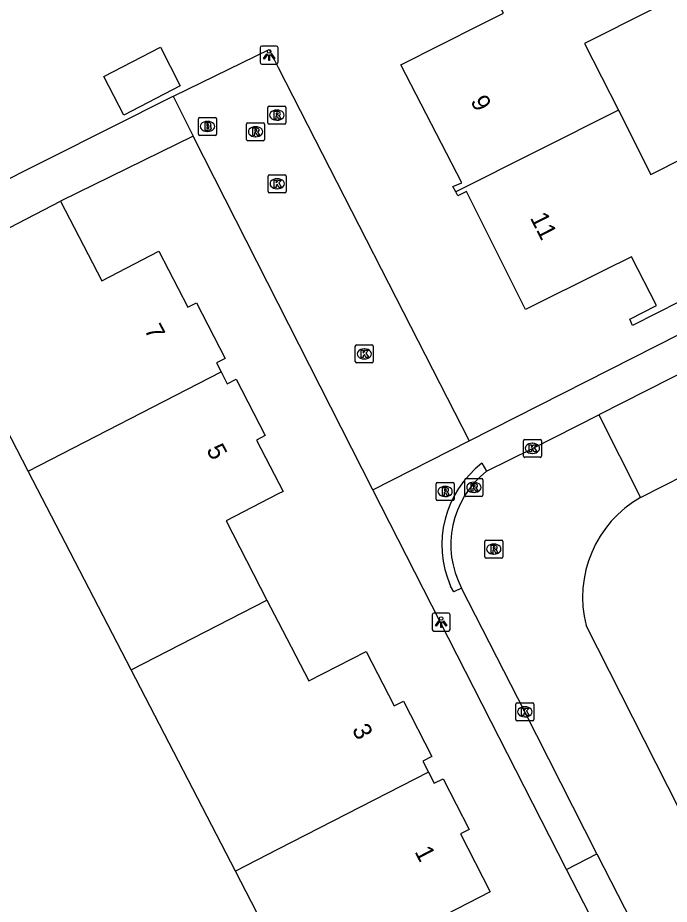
# Model space of a CAD drawing. Extents: x 162722 to 165099, y 384721 to 386283.
# Drawn here: x 163985.51 to 164021.74, y 385039.4 to 385088.69 of the extents above; entities that cross this region are included whole.
import ezdxf

# ---------------------------------------------------------------- set-up
doc = ezdxf.new("R2010")
doc.units = 0
for name, color, linetype in [('IMGEO_Brandkraan', 7, 'Continuous'), ('IMGEO_Kolk', 7, 'Continuous'), ('IMGEO_Lichtpunt', 7, 'Continuous'), ('IMGEO_Pand', 7, 'Continuous'), ('IMGEO_Pand_nummerreeks', 7, 'Continuous'), ('IMGEO_Rijbaan_lokaal_open', 7, 'Continuous'), ('IMGEO_Rioolput', 7, 'Continuous'), ('IMGEO_Voetpad_open', 7, 'Continuous')]:
    doc.layers.add(name, color=color, linetype=linetype)

msp = doc.modelspace()

# ---------------------------------------------------------------- linework, layer by layer
at = {"layer": 'IMGEO_Brandkraan'}
for p, q in [((163995.563, 385082.219), (163995.563, 385083.071)), ((163995.638, 385083.145), (163996.49, 385083.145)), ((163996.051, 385082.925), (163996.076, 385082.925)), ((163996.564, 385083.071), (163996.564, 385082.219)), ((163996.074, 385082.365), (163996.049, 385082.365)), ((163996.49, 385082.145), (163995.638, 385082.145))]:
    msp.add_line(p, q, dxfattribs=at)
for points in [[(163995.563, 385082.219), (163995.563, 385083.071)], [(163995.638, 385083.145), (163996.49, 385083.145)], [(163995.911, 385082.845), (163995.911, 385082.445), (163996.124, 385082.445)], [(163996.142, 385082.845), (163995.911, 385082.845)], [(163996.564, 385083.071), (163996.564, 385082.219)], [(163996.09, 385082.764), (163996.036, 385082.764), (163996.036, 385082.688)], [(163996.036, 385082.688), (163996.089, 385082.688)], [(163996.098, 385082.612), (163996.036, 385082.612), (163996.036, 385082.531)], [(163996.036, 385082.531), (163996.098, 385082.531)], [(163996.49, 385082.145), (163995.638, 385082.145)]]:
    msp.add_lwpolyline(points, dxfattribs=at)
for centre, radius, start, end in [((163995.64, 385083.069), 0.0765, 91.552, 178.448), ((163995.64, 385083.069), 0.0765, 91.552, 178.448), ((163996.146, 385082.7), 0.145, 59.4692, 91.5367), ((163996.171, 385082.747), 0.0922, 285.5137, 58.1501), ((163996.488, 385083.069), 0.0765, 1.552, 88.448), ((163996.488, 385083.069), 0.0765, 1.552, 88.448), ((163996.091, 385082.726), 0.0379, 267.8285, 90.9355), ((163996.099, 385082.571), 0.0404, 269.8759, 90.5077), ((163996.13, 385082.696), 0.251, 268.6676, 293.5347), ((163996.176, 385082.555), 0.105, 301.3115, 78.989), ((163995.64, 385082.221), 0.0765, 181.552, 268.448), ((163995.64, 385082.221), 0.0765, 181.552, 268.448), ((163996.488, 385082.221), 0.0765, 271.552, 358.448), ((163996.488, 385082.221), 0.0765, 271.552, 358.448)]:
    msp.add_arc(centre, radius, start, end, dxfattribs=at)
for centre, major_axis, ratio, start_param, end_param in [((163996.05, 385082.645), (-0.387, 0.002), 0.722429, 4.712389, 7.853982), ((163996.075, 385082.645), (-0.39, 0.002), 0.717154, 1.570796, 4.712389)]:
    msp.add_ellipse(centre, major_axis=major_axis, ratio=ratio, start_param=start_param, end_param=end_param, dxfattribs=at)
at = {"layer": 'IMGEO_Kolk'}
for p, q in [((163999.444, 385079.032), (163999.444, 385079.884)), ((163999.519, 385079.958), (164000.371, 385079.958)), ((164000.445, 385079.884), (164000.445, 385079.032)), ((163999.932, 385079.738), (163999.957, 385079.738)), ((164000.371, 385078.958), (163999.519, 385078.958)), ((163999.955, 385079.178), (163999.93, 385079.178)), ((164004.36, 385070.498), (164005.212, 385070.498)), ((164004.285, 385069.572), (164004.285, 385070.424)), ((164004.773, 385070.278), (164004.798, 385070.278)), ((164005.286, 385070.424), (164005.286, 385069.572)), ((164004.796, 385069.718), (164004.771, 385069.718)), ((164005.212, 385069.498), (164004.36, 385069.498)), ((164013.631, 385064.321), (164013.631, 385065.173)), ((164013.706, 385065.247), (164014.558, 385065.247)), ((164014.632, 385065.173), (164014.632, 385064.321)), ((164014.119, 385065.027), (164014.144, 385065.027)), ((164014.558, 385064.247), (164013.706, 385064.247)), ((164014.142, 385064.467), (164014.117, 385064.467)), ((164013.21, 385049.672), (164013.21, 385050.524)), ((164013.285, 385050.598), (164014.137, 385050.598)), ((164013.698, 385050.378), (164013.723, 385050.378)), ((164014.211, 385050.524), (164014.211, 385049.672)), ((164013.721, 385049.818), (164013.696, 385049.818)), ((164014.137, 385049.598), (164013.285, 385049.598))]:
    msp.add_line(p, q, dxfattribs=at)
for points in [[(163999.444, 385079.032), (163999.444, 385079.884)], [(163999.519, 385079.958), (164000.371, 385079.958)], [(164000.445, 385079.884), (164000.445, 385079.032)], [(163999.765, 385079.658), (163999.888, 385079.658), (163999.888, 385079.507), (164000.018, 385079.658), (164000.182, 385079.658), (164000.036, 385079.507), (164000.189, 385079.258), (164000.037, 385079.258), (163999.952, 385079.422), (163999.888, 385079.355), (163999.888, 385079.258), (163999.765, 385079.258), (163999.765, 385079.658)], [(164000.371, 385078.958), (163999.519, 385078.958)], [(164004.36, 385070.498), (164005.212, 385070.498)], [(164004.285, 385069.572), (164004.285, 385070.424)], [(164004.606, 385070.198), (164004.729, 385070.198), (164004.729, 385070.047), (164004.859, 385070.198), (164005.023, 385070.198), (164004.877, 385070.047), (164005.03, 385069.798), (164004.878, 385069.798), (164004.793, 385069.962), (164004.729, 385069.895), (164004.729, 385069.798), (164004.606, 385069.798), (164004.606, 385070.198)], [(164005.286, 385070.424), (164005.286, 385069.572)], [(164005.212, 385069.498), (164004.36, 385069.498)], [(164013.631, 385064.321), (164013.631, 385065.173)], [(164013.706, 385065.247), (164014.558, 385065.247)], [(164014.632, 385065.173), (164014.632, 385064.321)], [(164013.952, 385064.947), (164014.075, 385064.947), (164014.075, 385064.796), (164014.205, 385064.947), (164014.369, 385064.947), (164014.223, 385064.796), (164014.376, 385064.547), (164014.224, 385064.547), (164014.139, 385064.711), (164014.075, 385064.644), (164014.075, 385064.547), (164013.952, 385064.547), (164013.952, 385064.947)], [(164014.558, 385064.247), (164013.706, 385064.247)], [(164013.21, 385049.672), (164013.21, 385050.524)], [(164013.285, 385050.598), (164014.137, 385050.598)], [(164013.531, 385050.298), (164013.654, 385050.298), (164013.654, 385050.147), (164013.784, 385050.298), (164013.948, 385050.298), (164013.802, 385050.147), (164013.955, 385049.898), (164013.803, 385049.898), (164013.718, 385050.062), (164013.654, 385049.995), (164013.654, 385049.898), (164013.531, 385049.898), (164013.531, 385050.298)], [(164014.211, 385050.524), (164014.211, 385049.672)], [(164014.137, 385049.598), (164013.285, 385049.598)]]:
    msp.add_lwpolyline(points, dxfattribs=at)
for centre, start, end in [((163999.521, 385079.882), 91.552, 178.448), ((163999.521, 385079.882), 91.552, 178.448), ((164000.369, 385079.882), 1.552, 88.448), ((164000.369, 385079.882), 1.552, 88.448), ((163999.521, 385079.034), 181.552, 268.448), ((163999.521, 385079.034), 181.552, 268.448), ((164000.369, 385079.034), 271.552, 358.448), ((164000.369, 385079.034), 271.552, 358.448), ((164004.362, 385070.422), 91.552, 178.448), ((164004.362, 385070.422), 91.552, 178.448), ((164005.21, 385070.422), 1.552, 88.448), ((164005.21, 385070.422), 1.552, 88.448), ((164004.362, 385069.574), 181.552, 268.448), ((164004.362, 385069.574), 181.552, 268.448), ((164005.21, 385069.574), 271.552, 358.448), ((164005.21, 385069.574), 271.552, 358.448), ((164013.708, 385065.171), 91.552, 178.448), ((164013.708, 385065.171), 91.552, 178.448), ((164014.556, 385065.171), 1.552, 88.448), ((164014.556, 385065.171), 1.552, 88.448), ((164013.708, 385064.323), 181.552, 268.448), ((164013.708, 385064.323), 181.552, 268.448), ((164014.556, 385064.323), 271.552, 358.448), ((164014.556, 385064.323), 271.552, 358.448), ((164013.287, 385050.522), 91.552, 178.448), ((164013.287, 385050.522), 91.552, 178.448), ((164014.135, 385050.522), 1.552, 88.448), ((164014.135, 385050.522), 1.552, 88.448), ((164013.287, 385049.674), 181.552, 268.448), ((164013.287, 385049.674), 181.552, 268.448), ((164014.135, 385049.674), 271.552, 358.448), ((164014.135, 385049.674), 271.552, 358.448)]:
    msp.add_arc(centre, 0.0765, start, end, dxfattribs=at)
for centre, major_axis, ratio, start_param, end_param in [((163999.931, 385079.458), (-0.387, 0.002), 0.722429, 4.712389, 7.853982), ((163999.956, 385079.458), (-0.39, 0.002), 0.717154, 1.570796, 4.712389), ((164004.772, 385069.998), (-0.387, 0.002), 0.722429, 4.712389, 7.853982), ((164004.797, 385069.998), (-0.39, 0.002), 0.717154, 1.570796, 4.712389), ((164014.118, 385064.747), (-0.387, 0.002), 0.722429, 4.712389, 7.853982), ((164014.143, 385064.747), (-0.39, 0.002), 0.717154, 1.570796, 4.712389), ((164013.697, 385050.098), (-0.387, 0.002), 0.722429, 4.712389, 7.853982), ((164013.722, 385050.098), (-0.39, 0.002), 0.717154, 1.570796, 4.712389)]:
    msp.add_ellipse(centre, major_axis=major_axis, ratio=ratio, start_param=start_param, end_param=end_param, dxfattribs=at)
at = {"layer": 'IMGEO_Lichtpunt'}
for p, q in [((163998.994, 385087.017), (163998.994, 385086.21)), ((163998.994, 385087.017), (163998.994, 385086.21)), ((163999.896, 385087.112), (163999.088, 385087.112)), ((163999.896, 385087.112), (163999.088, 385087.112)), ((163999.99, 385086.21), (163999.99, 385087.017)), ((163999.99, 385086.21), (163999.99, 385087.017)), ((163999.088, 385086.116), (163999.896, 385086.116)), ((163999.088, 385086.116), (163999.896, 385086.116)), ((164008.561, 385055.488), (164008.561, 385054.681)), ((164008.561, 385055.488), (164008.561, 385054.681)), ((164009.463, 385055.583), (164008.655, 385055.583)), ((164009.463, 385055.583), (164008.655, 385055.583)), ((164009.557, 385054.681), (164009.557, 385055.488)), ((164009.557, 385054.681), (164009.557, 385055.488)), ((164008.655, 385054.587), (164009.463, 385054.587)), ((164008.655, 385054.587), (164009.463, 385054.587))]:
    msp.add_line(p, q, dxfattribs=at)
for points in [[(163999.368, 385086.681), (163999.407, 385086.653), (163999.219, 385086.391), (163999.181, 385086.418), (163999.368, 385086.681)], [(163999.47, 385086.633), (163999.517, 385086.633), (163999.517, 385086.311), (163999.47, 385086.311), (163999.47, 385086.633)], [(163999.58, 385086.653), (163999.618, 385086.68), (163999.805, 385086.418), (163999.766, 385086.39), (163999.58, 385086.653)], [(164008.935, 385055.152), (164008.974, 385055.124), (164008.786, 385054.862), (164008.748, 385054.889), (164008.935, 385055.152)], [(164009.037, 385055.104), (164009.084, 385055.104), (164009.084, 385054.782), (164009.037, 385054.782), (164009.037, 385055.104)], [(164009.147, 385055.124), (164009.185, 385055.151), (164009.372, 385054.889), (164009.333, 385054.861), (164009.147, 385055.124)]]:
    msp.add_lwpolyline(points, dxfattribs=at)
for centre in [(163999.493, 385086.815), (164009.06, 385055.286)]:
    msp.add_circle(centre, 0.0994, dxfattribs=at)
for centre, start, end in [((163999.088, 385087.017), 90, 180), ((163999.088, 385087.017), 90, 180), ((163999.896, 385087.017), 0, 90), ((163999.896, 385087.017), 0, 90), ((163999.088, 385086.21), 180, 270), ((163999.088, 385086.21), 180, 270), ((163999.896, 385086.21), 270, 0), ((163999.896, 385086.21), 270, 360), ((164008.655, 385055.488), 90, 180), ((164008.655, 385055.488), 90, 180), ((164009.463, 385055.488), 0, 90), ((164009.463, 385055.488), 0, 90), ((164008.655, 385054.681), 180, 270), ((164008.655, 385054.681), 180, 270), ((164009.463, 385054.681), 270, 0), ((164009.463, 385054.681), 270, 360)]:
    msp.add_arc(centre, 0.0946, start, end, dxfattribs=at)
at = {"layer": 'IMGEO_Pand'}
for points in [[(164009.873, 385079.005), (164009.715, 385079.311), (164010.213, 385079.511), (164006.813, 385086.073), (164011.225, 385088.298), (164012.52, 385088.951), (164011.134, 385091.702), (164009.785, 385091.022), (164009.615, 385091.362), (164014.08, 385093.614), (164017.599, 385095.388), (164020.752, 385089.137), (164017.038, 385087.265), (164018.915, 385083.544)], [(163994.552, 385084.909), (163991.41, 385083.281), (163990.302, 385085.419), (163993.444, 385087.047), (163994.552, 385084.909)], [(164018.915, 385083.544), (164020.718, 385079.969), (164024.433, 385081.843), (164025.345, 385080.037), (164025.622, 385079.488), (164027.599, 385075.574), (164019.7, 385071.578), (164019.542, 385071.935), (164021.035, 385072.685), (164019.633, 385075.392), (164018.102, 385074.63), (164013.755, 385072.466), (164010.47, 385079.026), (164009.984, 385078.791), (164009.873, 385079.005)], [(164018.915, 385083.544), (164009.873, 385079.005)], [(163980.354, 385074.579), (163987.891, 385078.484)], [(163987.891, 385078.484), (163990.186, 385074.054), (163993.367, 385075.701), (163994.964, 385072.596), (163995.446, 385072.846), (163997.051, 385069.748), (163996.56, 385069.495), (163996.817, 385068.994)], [(163986.101, 385063.481), (163982.654, 385070.14), (163980.354, 385074.579)], [(163986.101, 385063.481), (163996.817, 385068.994)], [(163996.817, 385068.994), (163997.158, 385068.331), (163997.653, 385068.585), (163999.273, 385065.459), (163998.793, 385065.21), (164000.272, 385062.355), (164000, 385062.214), (163997.099, 385060.71), (163999.373, 385056.311)], [(163991.825, 385052.424), (163986.101, 385063.481)], [(163991.825, 385052.424), (163999.373, 385056.311)], [(163999.373, 385056.311), (164000, 385055.098), (164001.698, 385051.814), (164004.886, 385053.449), (164006.448, 385050.435), (164006.957, 385050.696), (164008.542, 385047.605), (164008.046, 385047.35), (164008.358, 385046.749)], [(163997.619, 385041.233), (163991.825, 385052.424)], [(164008.358, 385046.749), (164008.678, 385046.125), (164009.171, 385046.378), (164010.618, 385043.557), (164010.125, 385043.304), (164011.777, 385040.081), (164008.734, 385038.521), (164010.944, 385034.211), (164006.495, 385031.929), (164003.287, 385030.284), (164000, 385036.633), (163997.619, 385041.233)], [(164008.358, 385046.749), (164000, 385042.456), (163997.619, 385041.233)]]:
    msp.add_lwpolyline(points, dxfattribs=at)
at = {"layer": 'IMGEO_Rijbaan_lokaal_open'}
for points in [[(163994.161, 385084.326), (163994.214, 385084.352), (163999.488, 385086.926), (164000, 385085.924), (164010.614, 385065.161)], [(163994.161, 385084.326), (163995.272, 385082.112)], [(164005.266, 385062.437), (164000, 385072.804), (163995.272, 385082.112)], [(164041.383, 385078.606), (164024.526, 385070.005), (164017.821, 385066.613)], [(164020.147, 385062.015), (164032.566, 385068.313), (164048.996, 385076.628), (164053.146, 385078.642)], [(164011.571, 385063.47), (164014.132, 385064.747), (164017.821, 385066.613)], [(164017.821, 385066.613), (164020.147, 385062.015)], [(164005.266, 385062.437), (164010.614, 385065.161)], [(164017.722, 385042.203), (164013.711, 385050.098), (164010.195, 385056.975)], [(164040.957, 385008.624), (164040.599, 385008.534), (164030.122, 385029.274), (164017.119, 385054.888)], [(164017.722, 385042.203), (164019.645, 385038.43)]]:
    msp.add_lwpolyline(points, dxfattribs=at)
for centre, radius, start, end in [((164014.792, 385059.394), 5.195, 128.319, 207.7579), ((164023.299, 385056.469), 6.379, 119.6095, 194.3528)]:
    msp.add_arc(centre, radius, start, end, dxfattribs=at)
at = {"layer": 'IMGEO_Rioolput'}
for p, q in [((163999.422, 385082.847), (163999.422, 385083.699)), ((163999.497, 385083.773), (164000.349, 385083.773)), ((163999.91, 385083.553), (163999.935, 385083.553)), ((164000.423, 385083.699), (164000.423, 385082.847)), ((163998.313, 385082.851), (163999.165, 385082.851)), ((163999.933, 385082.993), (163999.908, 385082.993)), ((163998.238, 385081.925), (163998.238, 385082.777)), ((163998.726, 385082.631), (163998.751, 385082.631)), ((163999.239, 385082.777), (163999.239, 385081.925)), ((164000.349, 385082.773), (163999.497, 385082.773)), ((163999.165, 385081.851), (163998.313, 385081.851)), ((163998.749, 385082.071), (163998.724, 385082.071)), ((164008.776, 385061.923), (164008.776, 385062.775)), ((164008.851, 385062.849), (164009.703, 385062.849)), ((164009.264, 385062.629), (164009.289, 385062.629)), ((164009.777, 385062.775), (164009.777, 385061.923)), ((164010.377, 385062.152), (164010.377, 385063.004)), ((164010.452, 385063.078), (164011.304, 385063.078)), ((164010.865, 385062.858), (164010.89, 385062.858)), ((164011.378, 385063.004), (164011.378, 385062.152)), ((164010.888, 385062.298), (164010.863, 385062.298)), ((164009.703, 385061.849), (164008.851, 385061.849)), ((164009.287, 385062.069), (164009.262, 385062.069)), ((164011.304, 385062.078), (164010.452, 385062.078)), ((164011.558, 385059.645), (164012.41, 385059.645)), ((164011.483, 385058.719), (164011.483, 385059.571)), ((164011.971, 385059.425), (164011.996, 385059.425)), ((164012.484, 385059.571), (164012.484, 385058.719)), ((164011.994, 385058.865), (164011.969, 385058.865)), ((164012.41, 385058.645), (164011.558, 385058.645))]:
    msp.add_line(p, q, dxfattribs=at)
for points in [[(163999.422, 385082.847), (163999.422, 385083.699)], [(163999.497, 385083.773), (164000.349, 385083.773)], [(164000.011, 385083.471), (163999.759, 385083.473), (163999.759, 385083.073)], [(163999.937, 385083.392), (163999.883, 385083.392), (163999.883, 385083.311)], [(163999.883, 385083.311), (163999.935, 385083.311)], [(164000.423, 385083.699), (164000.423, 385082.847)], [(163998.313, 385082.851), (163999.165, 385082.851)], [(163999.759, 385083.073), (163999.883, 385083.073), (163999.883, 385083.235), (163999.894, 385083.235)], [(163999.941, 385083.206), (164000.012, 385083.073), (164000.152, 385083.073), (164000.087, 385083.199)], [(163998.238, 385081.925), (163998.238, 385082.777)], [(163998.827, 385082.549), (163998.575, 385082.551), (163998.575, 385082.151)], [(163998.753, 385082.47), (163998.699, 385082.47), (163998.699, 385082.389)], [(163998.699, 385082.389), (163998.751, 385082.389)], [(163999.239, 385082.777), (163999.239, 385081.925)], [(164000.349, 385082.773), (163999.497, 385082.773)], [(163999.165, 385081.851), (163998.313, 385081.851)], [(163998.575, 385082.151), (163998.699, 385082.151), (163998.699, 385082.313), (163998.71, 385082.313)], [(163998.757, 385082.284), (163998.828, 385082.151), (163998.968, 385082.151), (163998.903, 385082.277)], [(164008.776, 385061.923), (164008.776, 385062.775)], [(164008.851, 385062.849), (164009.703, 385062.849)], [(164009.777, 385062.775), (164009.777, 385061.923)], [(164010.377, 385062.152), (164010.377, 385063.004)], [(164010.452, 385063.078), (164011.304, 385063.078)], [(164010.966, 385062.776), (164010.714, 385062.778), (164010.714, 385062.378)], [(164010.892, 385062.697), (164010.838, 385062.697), (164010.838, 385062.616)], [(164010.838, 385062.616), (164010.89, 385062.616)], [(164011.378, 385063.004), (164011.378, 385062.152)], [(164009.365, 385062.547), (164009.113, 385062.549), (164009.113, 385062.149)], [(164009.113, 385062.149), (164009.237, 385062.149), (164009.237, 385062.311), (164009.248, 385062.311)], [(164009.291, 385062.468), (164009.237, 385062.468), (164009.237, 385062.387)], [(164009.237, 385062.387), (164009.289, 385062.387)], [(164009.295, 385062.282), (164009.366, 385062.149), (164009.506, 385062.149), (164009.441, 385062.275)], [(164010.714, 385062.378), (164010.838, 385062.378), (164010.838, 385062.54), (164010.849, 385062.54)], [(164010.896, 385062.511), (164010.967, 385062.378), (164011.107, 385062.378), (164011.042, 385062.504)], [(164009.703, 385061.849), (164008.851, 385061.849)], [(164011.304, 385062.078), (164010.452, 385062.078)], [(164011.558, 385059.645), (164012.41, 385059.645)], [(164011.483, 385058.719), (164011.483, 385059.571)], [(164012.072, 385059.343), (164011.82, 385059.345), (164011.82, 385058.945)], [(164011.998, 385059.264), (164011.944, 385059.264), (164011.944, 385059.183)], [(164011.944, 385059.183), (164011.996, 385059.183)], [(164012.484, 385059.571), (164012.484, 385058.719)], [(164011.82, 385058.945), (164011.944, 385058.945), (164011.944, 385059.107), (164011.955, 385059.107)], [(164012.002, 385059.078), (164012.073, 385058.945), (164012.213, 385058.945), (164012.148, 385059.071)], [(164012.41, 385058.645), (164011.558, 385058.645)]]:
    msp.add_lwpolyline(points, dxfattribs=at)
for centre, radius, start, end in [((163999.499, 385083.697), 0.0765, 91.552, 178.448), ((163999.499, 385083.697), 0.0765, 91.552, 178.448), ((163999.919, 385083.5), 0.19, 274.7715, 282.9687), ((163999.943, 385083.296), 0.0964, 77.0061, 93.1865), ((163999.957, 385083.353), 0.0378, 276.6634, 79.6772), ((164000.01, 385083.361), 0.109, 350.3612, 89.416), ((164000.008, 385083.361), 0.112, 277.5842, 350.9817), ((164000.347, 385083.697), 0.0765, 1.552, 88.448), ((164000.347, 385083.697), 0.0765, 1.552, 88.448), ((163998.315, 385082.775), 0.0765, 91.552, 178.448), ((163998.315, 385082.775), 0.0765, 91.552, 178.448), ((163999.163, 385082.775), 0.0765, 1.552, 88.448), ((163999.163, 385082.775), 0.0765, 1.552, 88.448), ((163999.499, 385082.849), 0.0765, 181.552, 268.448), ((163999.499, 385082.849), 0.0765, 181.552, 268.448), ((163999.893, 385083.182), 0.0533, 26.0293, 88.6989), ((163999.992, 385083.146), 0.108, 29.5134, 73.7905), ((164000.347, 385082.849), 0.0765, 271.552, 358.448), ((164000.347, 385082.849), 0.0765, 271.552, 358.448), ((163998.735, 385082.578), 0.19, 274.7715, 282.9687), ((163998.759, 385082.374), 0.0964, 77.0061, 93.1865), ((163998.773, 385082.431), 0.0378, 276.6634, 79.6772), ((163998.826, 385082.439), 0.109, 350.3612, 89.416), ((163998.824, 385082.439), 0.112, 277.5842, 350.9817), ((163998.808, 385082.224), 0.108, 29.5134, 73.7905), ((163998.315, 385081.927), 0.0765, 181.552, 268.448), ((163998.315, 385081.927), 0.0765, 181.552, 268.448), ((163998.709, 385082.26), 0.0533, 26.0293, 88.6989), ((163999.163, 385081.927), 0.0765, 271.552, 358.448), ((163999.163, 385081.927), 0.0765, 271.552, 358.448), ((164008.853, 385062.773), 0.0765, 91.552, 178.448), ((164008.853, 385062.773), 0.0765, 91.552, 178.448), ((164009.701, 385062.773), 0.0765, 1.552, 88.448), ((164009.701, 385062.773), 0.0765, 1.552, 88.448), ((164010.454, 385063.002), 0.0765, 91.552, 178.448), ((164010.454, 385063.002), 0.0765, 91.552, 178.448), ((164010.874, 385062.805), 0.19, 274.7715, 282.9687), ((164010.898, 385062.601), 0.0964, 77.0061, 93.1865), ((164010.912, 385062.658), 0.0378, 276.6634, 79.6772), ((164010.965, 385062.666), 0.109, 350.3612, 89.416), ((164010.963, 385062.666), 0.112, 277.5842, 350.9817), ((164011.302, 385063.002), 0.0765, 1.552, 88.448), ((164011.302, 385063.002), 0.0765, 1.552, 88.448), ((164009.247, 385062.258), 0.0533, 26.0293, 88.6989), ((164009.273, 385062.576), 0.19, 274.7715, 282.9687), ((164009.297, 385062.372), 0.0964, 77.0061, 93.1865), ((164009.311, 385062.429), 0.0378, 276.6634, 79.6772), ((164009.364, 385062.437), 0.109, 350.3612, 89.416), ((164009.362, 385062.437), 0.112, 277.5842, 350.9817), ((164009.346, 385062.222), 0.108, 29.5134, 73.7905), ((164010.454, 385062.154), 0.0765, 181.552, 268.448), ((164010.454, 385062.154), 0.0765, 181.552, 268.448), ((164010.848, 385062.487), 0.0533, 26.0293, 88.6989), ((164010.947, 385062.451), 0.108, 29.5134, 73.7905), ((164011.302, 385062.154), 0.0765, 271.552, 358.448), ((164011.302, 385062.154), 0.0765, 271.552, 358.448), ((164008.853, 385061.925), 0.0765, 181.552, 268.448), ((164008.853, 385061.925), 0.0765, 181.552, 268.448), ((164009.701, 385061.925), 0.0765, 271.552, 358.448), ((164009.701, 385061.925), 0.0765, 271.552, 358.448), ((164011.56, 385059.569), 0.0765, 91.552, 178.448), ((164011.56, 385059.569), 0.0765, 91.552, 178.448), ((164012.408, 385059.569), 0.0765, 1.552, 88.448), ((164012.408, 385059.569), 0.0765, 1.552, 88.448), ((164011.98, 385059.372), 0.19, 274.7715, 282.9687), ((164012.004, 385059.168), 0.0964, 77.0061, 93.1865), ((164012.018, 385059.225), 0.0378, 276.6634, 79.6772), ((164012.071, 385059.233), 0.109, 350.3612, 89.416), ((164012.069, 385059.233), 0.112, 277.5842, 350.9817), ((164011.56, 385058.721), 0.0765, 181.552, 268.448), ((164011.56, 385058.721), 0.0765, 181.552, 268.448), ((164011.954, 385059.054), 0.0533, 26.0293, 88.6989), ((164012.053, 385059.018), 0.108, 29.5134, 73.7905), ((164012.408, 385058.721), 0.0765, 271.552, 358.448), ((164012.408, 385058.721), 0.0765, 271.552, 358.448)]:
    msp.add_arc(centre, radius, start, end, dxfattribs=at)
for centre, major_axis, ratio, start_param, end_param in [((163999.909, 385083.273), (-0.387, 0.002), 0.722429, 4.712389, 7.853982), ((163999.934, 385083.273), (-0.39, 0.002), 0.717154, 1.570796, 4.712389), ((163998.725, 385082.351), (-0.387, 0.002), 0.722429, 4.712389, 7.853982), ((163998.75, 385082.351), (-0.39, 0.002), 0.717154, 1.570796, 4.712389), ((164009.263, 385062.349), (-0.387, 0.002), 0.722429, 4.712389, 7.853982), ((164009.288, 385062.349), (-0.39, 0.002), 0.717154, 1.570796, 4.712389), ((164010.864, 385062.578), (-0.387, 0.002), 0.722429, 4.712389, 7.853982), ((164010.889, 385062.578), (-0.39, 0.002), 0.717154, 1.570796, 4.712389), ((164011.97, 385059.145), (-0.387, 0.002), 0.722429, 4.712389, 7.853982), ((164011.995, 385059.145), (-0.39, 0.002), 0.717154, 1.570796, 4.712389)]:
    msp.add_ellipse(centre, major_axis=major_axis, ratio=ratio, start_param=start_param, end_param=end_param, dxfattribs=at)
at = {"layer": 'IMGEO_Voetpad_open'}
for points in [[(163976.768, 385075.599), (163994.161, 385084.326)], [(163995.272, 385082.112), (163987.891, 385078.484)], [(164010.614, 385065.161), (164040.517, 385080.323)], [(164011.328, 385063.915), (164011.571, 385063.47)], [(164016.024, 385041.339), (164005.266, 385062.437)], [(164010.195, 385056.975), (164009.757, 385056.761), (164009.584, 385057.091)], [(164016.024, 385041.339), (164017.722, 385042.203)], [(164017.949, 385037.586), (164016.024, 385041.339)]]:
    msp.add_lwpolyline(points, dxfattribs=at)
msp.add_arc((164014.79, 385059.395), 5.693, 127.4498, 203.8779, dxfattribs=at)

# ---------------------------------------------------------------- texts
at = {"layer": 'IMGEO_Pand_nummerreeks'}
for s, rotation, p in [('9', 297.0297, (164010.668, 385084.061)), ('11', 297.0297, (164013.982, 385077.567)), ('7', 297.3872, (163992.529, 385071.345)), ('5', 297.3872, (163995.985, 385064.674)), ('3', 297.1523, (164004.079, 385049.119)), ('1', 297.1523, (164007.563, 385042.326))]:
    msp.add_text(s, height=1, rotation=rotation, dxfattribs=at).set_placement(p)

doc.saveas('drawing.dxf')
